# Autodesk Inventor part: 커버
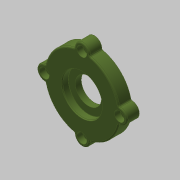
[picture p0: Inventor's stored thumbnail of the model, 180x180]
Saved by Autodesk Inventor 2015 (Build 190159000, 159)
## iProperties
Created: 2016-06
Part Number: 커버
Material: 알루미늄 6061
Document SubType Name: Modeling
Designer: mduedu
Density: 2.71 g/cm^3
Appearance: 올리브 녹색
Author: mduedu
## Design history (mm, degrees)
sketch "스케치1"
  geometry: C1 r 30 at (0, 0); 1 further point
  constraints: 1 centre point, 1 coincident
  dimensions: "d0" = 60 diameter of C1
extrude "돌출1" new body sketch "스케치1" distance "d2" = 10; taper "d3" = 0 deg
sketch "스케치5"
  geometry: C1 r 6 at (0, 30); 2 further points
  constraints: 2 vertical alignment, 1 centre point, 1 other
  dimensions: "d61" = 12 diameter of C1
extrude "돌출3" join sketch "스케치5" stored distance "d62" = 10; taper "d63" = 0 deg
sketch "스케치2"
  geometry: C1 r 21 at (0, 0); 1 further point
  constraints: 1 centre point, 1 coincident
  dimensions: "d4" = 42 diameter of C1
extrude "돌출2" join sketch "스케치2" distance "d6" = 3; taper "d7" = 0 deg
hole "구멍1" diameter "d11" = 35; stored, may be unused: countersink angle "d15" = 90 deg, drill point angle "d17" = 0 deg; dims "d9" = 10, "d10" = 10, "d12" = 6, "d13" = 4, "d14" = 2, "d16" = 3
hole "구멍2" diameter "d20" = 32; stored, may be unused: countersink angle "d24" = 90 deg, drill point angle "d26" = 0 deg; dims "d21" = 6, "d22" = 4, "d23" = 2, "d25" = 5.2, "d67" = 10, "d68" = 10
hole "구멍3" diameter "d29" = 21; stored, may be unused: countersink angle "d33" = 90 deg, drill point angle "d35" = 0 deg; dims "d27" = 10, "d28" = 10, "d30" = 6, "d31" = 4, "d32" = 2, "d34" = 5
fillet "모깎기2" dims "d36" = 3
fillet "모깎기3" dims "d37" = 0.1
chamfer "모따기1" distance "d38" = 0.75; stored, may be unused: second distance "d39" = 2, angle "d40" = 30 deg
chamfer "모따기2" distance "d42" = 0.5; stored, may be unused: second distance "d43" = 2, angle "d44" = 30 deg
sketch "스케치6"
  geometry: A1 r 30 centre (0, 0) between (29.4, 5.97) and (5.97, 29.4) reference; 3 further points
  constraints: 2 vertical alignment, 1 coincident, 3 other
hole "구멍5" sketch "스케치6" at (0, 30) diameter "d69" = 4.5; stored, may be unused: countersink angle "d73" = 90 deg, drill point angle "d75" = 118 deg; dims "d70" = 6, "d71" = 8, "d72" = 4.6, "d74" = 8
fillet "모깎기5" dims "d79" = 1
fillet "모깎기6" dims "d80" = 1
node "솔리드1"
pattern_circular "원형 패턴1" dims angle "d65" = 360 deg
pattern_circular "원형 패턴2" dims angle "d77" = 360 deg
node "투영된 루프1"
